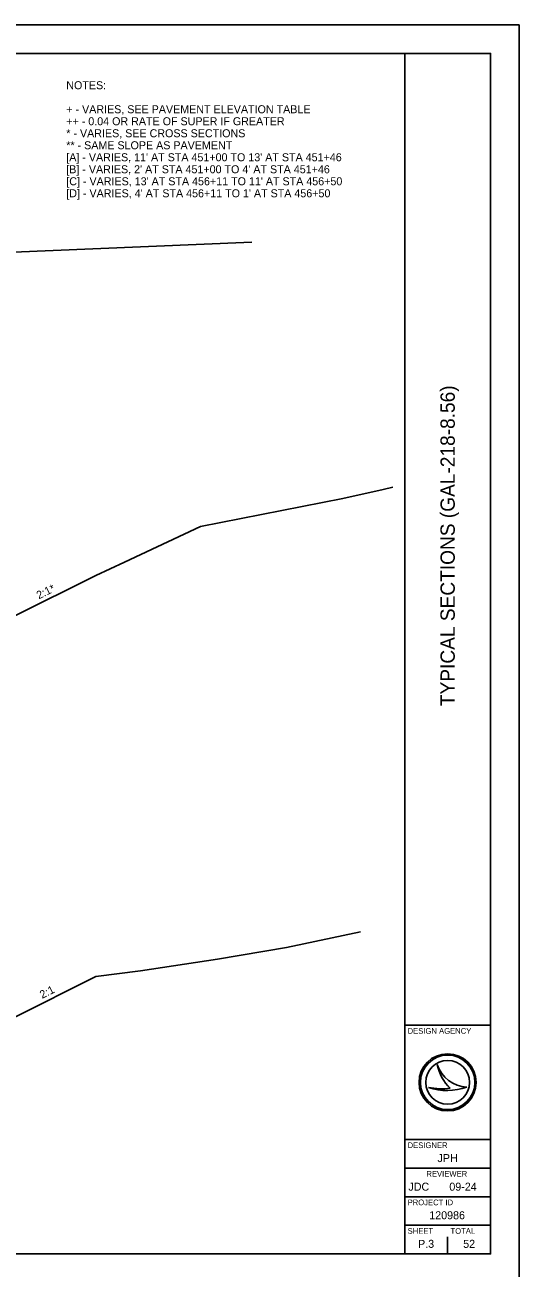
# Model space of a CAD drawing. Extents: x -396 to 156, y -166 to 172.
# Drawn here: x 76.1 to 102, y -98.8 to -33.6 of the extents above; entities that cross this region are included whole.
import ezdxf

# ---------------------------------------------------------------- set-up
doc = ezdxf.new("R2010")
doc.units = 0
for name, color, linetype in [('DT_X_Terrain_Ground_Line', 7, 'Continuous'), ('SH_Border', 7, 'Continuous'), ('SH_Cut_Line', 7, 'Continuous'), ('SH_Data', 7, 'Continuous'), ('TX_P_1', 7, 'Continuous'), ('TX_X_1', 7, 'Continuous'), ('XS_P_Finished_Grade', 7, 'Continuous')]:
    doc.layers.add(name, color=color, linetype=linetype)

msp = doc.modelspace()

# ---------------------------------------------------------------- linework, layer by layer
at = {"layer": 'DT_X_Terrain_Ground_Line'}
msp.add_line((77.135, -45.406), (87.983, -44.952), dxfattribs=at)
for points in [[(60.009, -42.647), (61.105, -42.788), (61.618, -42.796), (61.872, -42.883), (65.203, -45.006), (65.896, -45.563), (67.21, -46.432), (67.86, -46.385), (69.673, -46.238), (70.062, -46.268), (70.396, -46.262), (71.401, -46.242), (72.123, -45.888), (72.92, -45.583), (74.108, -45.544), (74.24, -45.527), (77.135, -45.406)], [(79.789, -62.452), (81.295, -61.748), (85.279, -59.881), (92.757, -58.404), (94.871, -57.936), (95.367, -57.821)], [(79.789, -83.504), (82.142, -83.203), (86.181, -82.585), (89.792, -81.975), (93.683, -81.15)]]:
    msp.add_lwpolyline(points, dxfattribs=at)
at = {"layer": 'SH_Border'}
for p, q in [((96, -98.053), (96, -35.053)), ((96, -86.053), (100.5, -86.053)), ((96, -92.053), (100.5, -92.053)), ((96, -93.553), (100.5, -93.553)), ((96, -95.053), (100.5, -95.053)), ((96, -96.553), (100.5, -96.553))]:
    msp.add_line(p, q, dxfattribs=at)
msp.add_lwpolyline([(4.5, -35.053), (100.5, -35.053), (100.5, -98.053), (4.5, -98.053)], close=True, dxfattribs=at)
at = {"layer": 'SH_Cut_Line'}
msp.add_lwpolyline([(0, -99.553), (102, -99.553), (102, -33.553), (0, -33.553)], close=True, dxfattribs=at)
at = {"layer": 'SH_Data'}
for p, q in [((97.702, -88.125), (97.702, -88.125)), ((97.252, -89.325), (97.251, -89.325)), ((98.25, -89.053), (98.25, -89.053)), ((99.262, -89.298), (99.262, -89.298)), ((98.25, -98.053), (98.25, -97.153)), ((97.125, -97.528), (97.125, -97.528))]:
    msp.add_line(p, q, dxfattribs=at)
for radius in [1.5, 1.43, 1.43, 1.147]:
    msp.add_circle((98.25, -89.053), radius, dxfattribs=at)
for centre, radius, start, end in [((99.348, -87.56), 1.74, 198.92567, 198.93195), ((100.04, -87.643), 2.387, 191.63793, 191.64215), ((99.348, -87.56), 1.74, 198.93195, 267.16574), ((100.04, -87.643), 2.387, 191.64215, 226.09467), ((98.218, -86.443), 3.039, 251.45274, 251.45764), ((98.218, -86.443), 3.039, 251.45764, 290.08324), ((97.944, -85.59), 3.798, 259.49639, 259.49952), ((97.944, -85.59), 3.798, 259.49952, 276.66723)]:
    msp.add_arc(centre, radius, start, end, dxfattribs=at)
at = {"layer": 'XS_P_Finished_Grade'}
for p, q in [((79.789, -62.452), (75.469, -64.612)), ((79.789, -83.504), (75.469, -85.664))]:
    msp.add_line(p, q, dxfattribs=at)

# ---------------------------------------------------------------- texts
at = {"layer": 'SH_Data'}
msp.add_text('TYPICAL SECTIONS (GAL-218-8.56)', height=0.75, rotation=90, dxfattribs=at).set_placement((98.625, -69.307))
for s, height, p in [('DESIGN AGENCY', 0.3, (96.15, -86.503)), ('DESIGNER', 0.3, (96.15, -92.503)), ('JPH', 0.42, (97.719, -93.238)), ('REVIEWER', 0.3, (97.135, -94.003)), ('JDC', 0.42, (96.191, -94.738)), ('09-24', 0.42, (98.339, -94.738)), ('PROJECT ID', 0.3, (96.15, -95.503)), ('120986', 0.42, (97.285, -96.238)), ('SHEET', 0.3, (96.15, -97.003)), ('TOTAL', 0.3, (98.4, -97.003)), ('P.3', 0.42, (96.698, -97.738)), ('52', 0.42, (99.064, -97.738))]:
    msp.add_text(s, height=height, dxfattribs=at).set_placement(p)
at = {"layer": 'TX_P_1'}
for s, p in [('2:1*', (76.806, -63.709)), ('2:1', (76.978, -84.675))]:
    msp.add_text(s, height=0.42, rotation=26.56505, dxfattribs=at).set_placement(p)
at = {"layer": 'TX_X_1'}
for s, p in [('NOTES:', (78.244, -36.932)), ('+ - VARIES, SEE PAVEMENT ELEVATION TABLE', (78.244, -38.192)), ('++ - 0.04 OR RATE OF SUPER IF GREATER', (78.244, -38.822)), ('* - VARIES, SEE CROSS SECTIONS', (78.244, -39.452)), ('** - SAME SLOPE AS PAVEMENT', (78.244, -40.082)), ("[A] - VARIES, 11' AT STA 451+00 TO 13' AT STA 451+46", (78.244, -40.712)), ("[B] - VARIES, 2' AT STA 451+00 TO 4' AT STA 451+46", (78.244, -41.342)), ("[C] - VARIES, 13' AT STA 456+11 TO 11' AT STA 456+50", (78.244, -41.972)), ("[D] - VARIES, 4' AT STA 456+11 TO 1' AT STA 456+50", (78.244, -42.602))]:
    msp.add_text(s, height=0.42, dxfattribs=at).set_placement(p)

doc.saveas('drawing.dxf')
